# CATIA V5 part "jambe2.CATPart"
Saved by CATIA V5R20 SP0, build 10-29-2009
Part number: jambe2
Bounding box of the stored display mesh (mm): x -325 to -225, y -1070 to -40, z 10 to 40
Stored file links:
  D:\Dropbox\Pack 1 sylvain\mmoreau\mmoreau\mmoreau\fin\jambe2.CATPart
  U:\think motion\fin\think motion2.CATProduct
  D:\Dropbox\Pack 1 sylvain\mmoreau\mmoreau\mmoreau\fin\Part1.CATPart
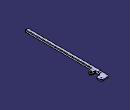
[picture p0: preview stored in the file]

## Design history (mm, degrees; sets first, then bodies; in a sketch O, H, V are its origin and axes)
Parameters
  LENGTH = 1000 mm
Set1
  Plane1: linked copy from another document
  Point1 to Point6: linked copy from another document
  Line1: linked copy from another document
  Plane2: linked copy from another document
  Point7: linked copy from another document
Body1 (main body)
  Sketch1 on Plane1, origin (-325, 0, 0), H (0, 1, 0), V (0, 0, 1)
    point P1 (-1070, 40)
    line L1 (-40, 30) -> (-40, 10)
    line L2 (-40, 10) -> (-1070, 10)
    line L3 (-1070, 10) -> (-1070, 40)
    reference projected line E1 (-70, 10) -> (-70, 50)
    reference projected point E4 (-70, 30)
    line L4 (-40, 30) -> (-140, 30)
    point P5 (-140, 30)
    line L5 (-140, 30) -> (-145.7735, 40)
    line L6 (-145.7735, 40) -> (-1070, 40)
    point P7 (-1070, 40)
    reference projected line E5 (-1070, 30) -> (-70, 30)
    distance L1 E1 = 30
    distance E4 L3 = 1000 {= LENGTH}
    distance L2 L6 = 30
    distance L1 P5 = 100
    distance L6 E5 = 10
    angle L5 L4 = 120
    distance L4 L2 = 20
    horizontal: L2 H, L4 H, L6 H
    vertical: L1 V, L3 V
    coincidence: P1 P7
  Pad1: profile Sketch1, direction (1, 0, 0), length 40
  Sketch2 on face of Pad1 from Sketch1.L2, origin (0, 0, 10), H (1, 0, 0), V (0, -1, 0)
    line L1 (-325, 110) -> (-225, 110)
    line L2 (-225, 110) -> (-225, 40)
    line L3 (-225, 40) -> (-325, 40)
    line L4 (-325, 40) -> (-325, 110)
    reference projected line E1 (-325, 1070) -> (-325, 40) from edge [start face of Pad1 | face of Pad1 from Sketch1.L2]
    reference projected line E2 (-325, 40) -> (-285, 40) from edge [face of Pad1 from Sketch1.L1 | face of Pad1 from Sketch1.L2]
    distance L1 L3 = 70
    distance L2 L4 = 100
    horizontal: L1 H, L3 H
    vertical: L2 V, L4 V
    coincidence: L4 E1, E2 L3
  Pad2: profile Sketch2, direction (0, 0, 1), length 20
  Sketch3 on face of Pad2, origin (-240.0576, -89.9953, 10), H (1, 0, 0), V (0, -1, 0)
    point P1 (-9.9424, -19.9953)
    reference projected point E1 (-9.9424, -19.9953) from Point1
    coincidence: P1 E1
  Hole1: placed by Sketch3, at (-250, -70, 10) direction (0, 0, 1), diameter 10, through (limit type 3)
  Sketch4 on face of Pad2, origin (-325, 0, 0), H (0, 1, 0), V (0, 0, 1)
    line L1 (-1070, 35) -> (-870, 35)
    line L2 (-870, 35) -> (-870, -84.0912)
    line L3 (-870, -84.0912) -> (-1070, -84.0912)
    line L4 (-1070, -84.0912) -> (-1070, 35)
    reference projected line E1 (-1070, 40) -> (-1070, 10)
    reference projected line E2 (-145.7735, 40) -> (-1070, 40)
    distance L2 L4 = 200
    distance L1 E2 = 5
    horizontal: L1 H, L3 H
    vertical: L2 V, L4 V
    coincidence: L4 E1
  Pocket1: profile Sketch4, direction (1, 0, 0), length 35
  Sketch5 on end face of Pocket1, origin (-290, 0, 0), H (0, -1, 0), V (0, 0, 1)
    circle A1 centre (1035, 16) radius 4
    point P1 (1035, 16)
    circle A2 centre (935, 16) radius 4
    point P2 (935, 16)
    reference projected line E1 (1070, 35) -> (1070, 10) from edge [end face of Pocket1 | face of Pad1 from Sketch1.L3]
    reference projected point E2 (1035, 16) from Point3
    reference projected point E3 (935, 16) from Point4
    reference projected point E4 (1035, 16) from Point5
    radius A1 = 4
    radius A2 = 4
    distance E1 E2 = 35 (reference)
    coincidence: P2 E3, P1 E4
  Pad3: profile Sketch5, direction (-1, 0, 0), length 35
  Fillet1: radius 20, on edge [face of Pad1 from Sketch1.L5 | face of Pad2]; edge [face of Pad2 from Sketch2.L1 | end face of Pad1]; edge [face of Pad2 from Sketch2.L2 | face of Pad2 from Sketch2.L1]; edge [face of Pad2 | face of Pad2 from Sketch2.L2]; edge [face of Pad2 | face of Pad2]
  Fillet2: radius 20, on edge [end face of Pocket1 | face of Pocket1 from Sketch4.L2]
  Sketch6 on face of Pad1 from Sketch1.L6, origin (0, 0, 40), H (1, 0, 0), V (0, 1, 0)
    arc A1 centre (-250, -200) radius 20 from (-246.527, -219.6962) to (-246.527, -180.3038) ccw
    point P1 (-250, -200)
    reference projected point E1 (-250, -200) from Point6
    line L1 (-285, -173.52) -> (-246.527, -180.3038)
    point P2 (-285, -173.52)
    line L2 (-285, -226.48) -> (-246.527, -219.6962)
    point P4 (-285, -226.48)
    reference intersected line E2 (-285, -145.7735) -> (-285, -1070) from end face of Pad1
    reference intersected line E3 (-285, -145.7735) -> (-285, -1070) from end face of Pad1
    reference projected line E4 (-250, -200) -> (-245, -200) from Line1
    reference projected line E5 (-250, -200) -> (-245, -200) from Line1
    line L3 (-285, -173.52) -> (-285, -226.48)
    radius A1 = 20
    angle E5 L1 = 10
    coincidence: P1 E1, P4 E2, P2 E3
    tangency: L2 A1, A1 L1
    symmetry: L1 L2 E4
    vertical: L3 V
  Pad4: profile Sketch6, direction (0, 0, -1), length 30
  Sketch7 on face of Pad4, origin (-273.7207, -217.1921, 40), H (1, 0, 0), V (0, 1, 0)
    point P1 (23.7207, 17.1921)
    reference projected point E1 (23.7207, 17.1921) from Point6
    coincidence: E1 P1
  Hole2: placed by Sketch7, at (-250, -200, 40) direction (0, 0, -1), diameter 10, through (limit type 3)
  Sketch8 on Plane2, origin (-250, 0, 0), H (0, 1, 0), V (0, 0, 1)
    line L1 (-170, 35) -> (-230, 35)
    line L2 (-230, 35) -> (-230, 19)
    line L3 (-230, 19) -> (-170, 19)
    line L4 (-170, 19) -> (-170, 35)
    reference projected point E1 (-200, 30) from Point7
    reference projected point E2 (-200, 30) from Point7
    reference projected point E3 (-200, 30) from Point7
    distance L4 E1 = 30
    distance E2 L2 = 30
    distance E3 L1 = 5
    distance L3 L1 = 16
    horizontal: L1 H, L3 H
    vertical: L2 V, L4 V
  Pocket2: profile Sketch8, direction (-1, 0, 0), length 30, mirrored extent
  Fillet3: radius 5, on edge [face of Pad2 | face of Pad4] (x2); edge [face of Pad4 | end face of Pad1] (x2)
  Fillet4: radius 2, on face of Pad1 from Sketch1.L3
